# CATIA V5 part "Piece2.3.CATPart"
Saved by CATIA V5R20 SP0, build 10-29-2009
Part number: Piece2.3
Bounding box of the stored display mesh (mm): x 0 to 100, y -50 to 259.019, z 86.603 to 111.247
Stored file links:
  C:\Users\Lambert\Desktop\IAO\Piece2.3.CATPart
  C:\Users\Lambert\Desktop\IAO\Produit1.CATProduct
  C:\Users\Lambert\Desktop\IAO\skl_general.CATPart
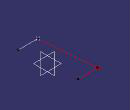
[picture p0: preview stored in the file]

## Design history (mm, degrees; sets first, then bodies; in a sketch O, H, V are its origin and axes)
Set1
  Point1 "B": linked copy from another document
  DatumPoint1 "C": linked copy from another document
  Plane1 "Plan_Ref": linked copy from another document
Set2
  Line1 "Bielle 2.3": type PtPt, FirstPoint Point1, SecondPoint DatumPoint1, Support Plane1
  Line2 "Axe_pivot_52": type Normal, RefPoint DatumPoint1, RefSkin Plane1, Start 0, End 100
  Line3 "Axe_pivot_12": type Normal, RefPoint Point1, RefSkin Plane1, Start 0, End 100
Body1 (main body)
